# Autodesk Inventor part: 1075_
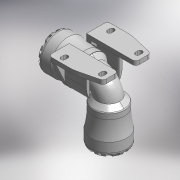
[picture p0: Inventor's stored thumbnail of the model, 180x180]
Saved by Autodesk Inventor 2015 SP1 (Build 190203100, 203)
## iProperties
Created: 2017-01
Part Number: 1075_
Material: PVC-Piping
Description: PLASSON WALL PLATE ELBOW 25X1/2" SERIES 1
Document SubType Name: Modeling
Designer: KIM
Mass: 122.736 g
Surface Area: 365.546 cm^2
Volume: 87.6688 cm^3
Density: 1.4 g/cm^3
Appearance: Smooth - White
Author: naamad
Title: SR1-ELBOW-BRACKET-20-CAT
Organization: PLASSON
Sending System: PRO/ENGINEER BY PARAMETRIC TECHNOLOGY CORPORATION, 2014000
Preprocessor: PRO/ENGINEER BY PARAMETRIC TECHNOLOGY CORPORATION, 2014000
Author: KIM
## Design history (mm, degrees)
derived "1075_.ipt"
feature "Solid1::1075_.ipt" dims "ScaleForDerivedMember" = 10
feature "Solid11::1075_.ipt" dims "ScaleForDerivedMember" = 10
tag "TaggingFeature1"
body "Solid1"
body "Solid2"
other parameters: "d3" = 25 [user parameter], "d4" = 47 [user parameter], "d5" = 31.25 [user parameter], "d6" = 20.16 [user parameter], "d7" = 48 [user parameter], "d9" = 41.36 [user parameter], "d13" = 3.96 [user parameter], "d14" = 7.92 [user parameter], "d26" = 74 [user parameter], "d39" = 6.3 [user parameter], "d41" = 6.3 [user parameter], "d42" = 0 [user parameter], "d44" = 360 deg [user parameter], "d46" = 8 deg [user parameter], "d47" = 8 deg [user parameter], "d48" = 0.5 [user parameter], "d49" = 0.5 [user parameter], "d51" = 0 [user parameter], "d53" = 360 deg [user parameter], "d55" = 0.25 [user parameter], "d61" = 2.5 [user parameter], "d69" = 90 deg [user parameter], "d71" = 4.658 [user parameter], "d72" = 0 [user parameter], "d73" = 0 [user parameter], "d74" = 5.5 [user parameter], "d78" = 28 [user parameter], "d91" = 28 [user parameter], "d98" = 6 [user parameter], "d99" = 0 [user parameter], "d100" = 4.5 [user parameter], "d101" = 19 [user parameter], "d102" = 29 [user parameter], "d103" = 0 [user parameter], "d105" = 0 [user parameter], "d107" = 0 [user parameter], "d117" = 2 [user parameter], "d120" = 28 [user parameter], "d121" = 39 [user parameter], "d122" = 98 [user parameter], "d123" = 31.2 [user parameter], "d125" = 0 [user parameter], "d126" = 4.68 [user parameter], "d128" = 39 [user parameter], "d129" = 3 [user parameter], "d130" = 3.5 [user parameter], "d131" = 3.5 [user parameter], "d132" = 6 [user parameter], "d134" = 0 [user parameter], "d_" = 25 [user parameter], "E_" = 47 [user parameter], "l_" = 48 [user parameter], "A_" = 74 [user parameter], "A_2" = 28 [user parameter], "L_" = 78 [user parameter], "H_" = 98 [user parameter], "d37" = 31.25 [user parameter], "d38" = 47 [user parameter], "d40" = 7.875 [user parameter]
